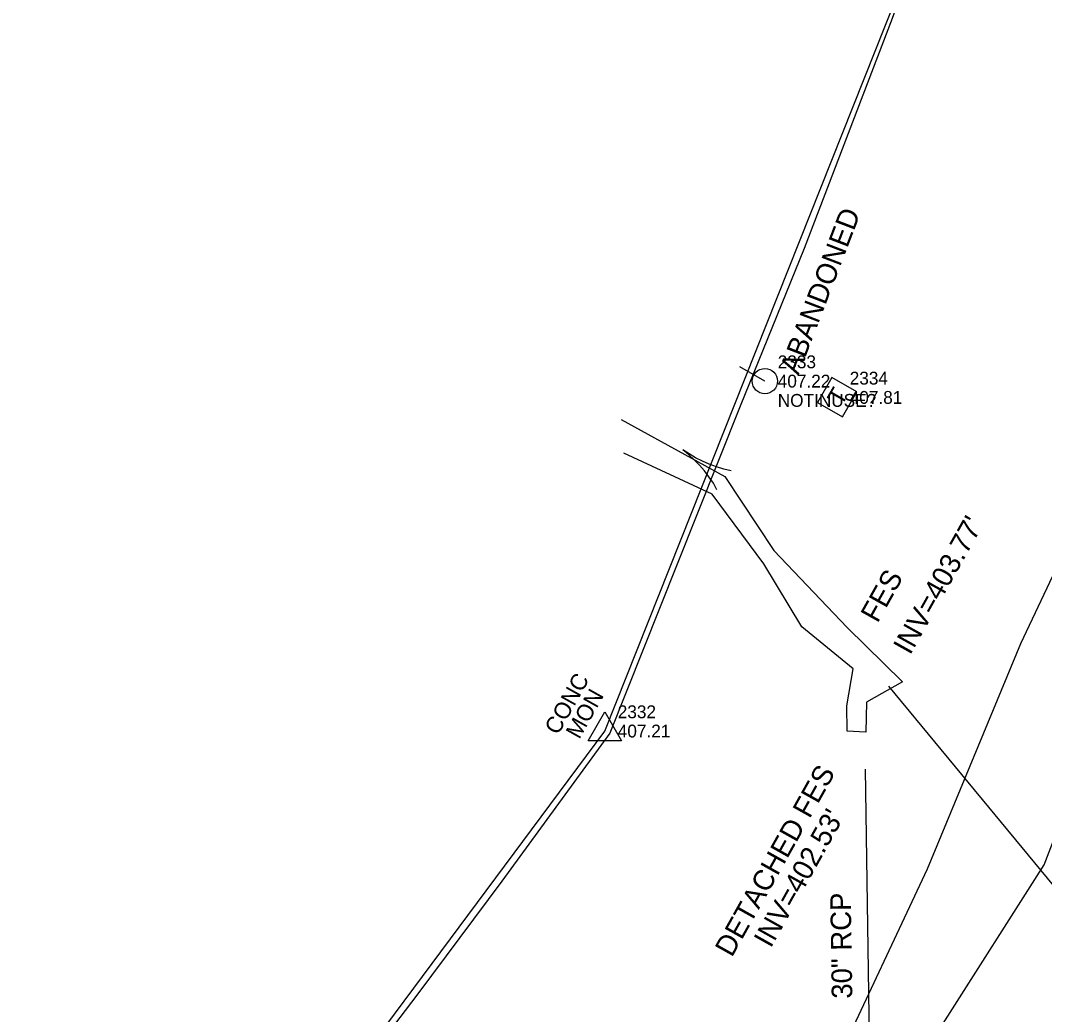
# Model space of a CAD drawing. Extents: x 2074109 to 2077820, y 741079 to 746031.
# Drawn here: x 2075888.4 to 2076087.4, y 744709.8 to 744903 of the extents above; entities that cross this region are included whole.
import ezdxf

# ---------------------------------------------------------------- set-up
doc = ezdxf.new("R2010")
doc.units = 0
for name, color, linetype in [('Exist Horizontal Alignment', 7, 'Continuous'), ('Exist Hydro Stream Flow Arrow CELL', 7, 'Continuous'), ('Exist Hydro Stream or Body of Water', 7, 'Continuous'), ('Exist Other Culture Fence Line', 7, 'Continuous'), ('Exist Right of Way Line', 7, 'Continuous'), ('Exist Right of Way Monument CELL', 7, 'Continuous'), ('Exist Right of Way Monument Cogo Elevation', 7, 'Continuous'), ('Exist Right of Way Monument Cogo Number', 7, 'Continuous'), ('Exist Right of Way Monument Text', 7, 'Continuous'), ('Exist Structure Minor Pipes RCP 30 Inch', 7, 'Continuous'), ('Exist Structure Minor Pipes RCP 30 Inch Invert', 7, 'Continuous'), ('Exist Structure Minor Pipes RCP 30 Inch Text', 7, 'Continuous'), ('Exist Structure Minor Pipes RCP 48 Inch', 7, 'Continuous'), ('Exist Structure Minor Pipes RCP 48 Inch Invert', 7, 'Continuous'), ('Exist Utilities Power Pole CELL', 7, 'Continuous'), ('Exist Utilities Power Pole Cogo Comment', 7, 'Continuous'), ('Exist Utilities Power Pole Cogo Elevation', 7, 'Continuous'), ('Exist Utilities Power Pole Cogo Number', 7, 'Continuous'), ('Exist Utilities Power Pole Text', 7, 'Continuous'), ('Exist Utilities Telephone Pedestal CELL', 7, 'Continuous'), ('Exist Utilities Telephone Pedestal Cogo Elevation', 7, 'Continuous'), ('Exist Utilities Telephone Pedestal Cogo Number', 7, 'Continuous'), ('Exist Utilities Telephone UG FO SUE LOS B', 7, 'Continuous'), ('Exist Vegetation Woods Line', 7, 'Continuous')]:
    doc.layers.add(name, color=color, linetype=linetype)

msp = doc.modelspace()

# ---------------------------------------------------------------- linework, layer by layer
at = {"layer": 'Exist Horizontal Alignment'}
for centre, radius, start, end in [((2065746.77, 748969.72), 11283.45, 330.581241, 339.398504), ((2074798.58, 745361.18), 1469.76, 306.18995, 339.08912)]:
    msp.add_arc(centre, radius, start, end, dxfattribs=at)
at = {"layer": 'Exist Hydro Stream Flow Arrow CELL'}
msp.add_line((2076021.1, 744816.63), (2076021.1, 744816.63), dxfattribs=at)
for points in [[(2076026.48, 744815.48), (2076025.05, 744815.8), (2076023.63, 744816.28), (2076022.24, 744816.77), (2076020.92, 744817.36), (2076019.6, 744818.04), (2076018.31, 744818.8), (2076017.09, 744819.61)], [(2076023.75, 744811.81), (2076023.04, 744813.09), (2076022.17, 744814.31), (2076021.3, 744815.5), (2076020.35, 744816.6), (2076019.32, 744817.66), (2076018.22, 744818.68), (2076017.09, 744819.61)]]:
    msp.add_lwpolyline(points, dxfattribs=at)
at = {"layer": 'Exist Hydro Stream or Body of Water'}
msp.add_lwpolyline([(2076005.14, 744825.46), (2076025.25, 744814.37), (2076034.83, 744800), (2076049.07, 744785.06), (2076059.84, 744774.47), (2076052.8, 744770.53), (2076052.7, 744764.69), (2076049.04, 744764.89), (2076049, 744769.8), (2076050.21, 744776.99), (2076040.24, 744785.17), (2076032.88, 744797.42), (2076022.8, 744810.99), (2076005.61, 744818.96)], dxfattribs=at)
at = {"layer": 'Exist Other Culture Fence Line'}
msp.add_lwpolyline([(2076162.42, 745176.79), (2076145.19, 745130.51), (2076128.17, 745085.01), (2076111.58, 745041.43), (2076096.68, 745003.97), (2076079.15, 744957.46), (2076063.26, 744918.47), (2076057.81, 744903.45), (2076040.7, 744858.73), (2076028.24, 744828.04), (2076015.85, 744797.06), (2076002.89, 744764.52), (2075981.92, 744735.72), (2075965.57, 744713.81), (2075953.66, 744698.14), (2075926.24, 744660.83), (2075903.14, 744629.48), (2075873.54, 744589.85)], dxfattribs=at)
at = {"layer": 'Exist Right of Way Line'}
for p, q in [((2076001.96, 744764.91), (2076072.08, 744941.45)), ((2075770.83, 744453.88), (2076001.96, 744764.91)), ((2076001.96, 744764.91), (2076001.96, 744764.91))]:
    msp.add_line(p, q, dxfattribs=at)
at = {"layer": 'Exist Right of Way Monument CELL'}
msp.add_line((2076001.96, 744764.91), (2076001.96, 744764.91), dxfattribs=at)
msp.add_lwpolyline([(2075998.71, 744763.02), (2076001.96, 744768.66), (2076005.2, 744763.02)], close=True, dxfattribs=at)
at = {"layer": 'Exist Structure Minor Pipes RCP 30 Inch'}
msp.add_line((2076053.85, 744676.49), (2076052.65, 744757.49), dxfattribs=at)
at = {"layer": 'Exist Structure Minor Pipes RCP 48 Inch'}
msp.add_line((2076057.12, 744773.62), (2076166.6, 744640.93), dxfattribs=at)
at = {"layer": 'Exist Utilities Power Pole CELL'}
for q in [(2076028.17, 744835.73), (2076033.06, 744832.94)]:
    msp.add_line((2076033.06, 744832.94), q, dxfattribs=at)
msp.add_circle((2076033.06, 744832.94), 2.45, dxfattribs=at)
at = {"layer": 'Exist Utilities Telephone Pedestal CELL'}
msp.add_line((2076047.05, 744829.77), (2076047.05, 744829.77), dxfattribs=at)
msp.add_lwpolyline([(2076048.15, 744826), (2076050.92, 744830.86), (2076046.06, 744833.63), (2076043.29, 744828.77), (2076048.15, 744826)], dxfattribs=at)
at = {"layer": 'Exist Utilities Telephone UG FO SUE LOS B'}
msp.add_lwpolyline([(2075937.23, 744341.86), (2075954.9, 744371.47), (2075967.47, 744402.74), (2075973.95, 744427.85), (2075977.39, 744451.86), (2075976.07, 744468.29), (2075977.43, 744509.14), (2075977.11, 744533.46), (2075991.55, 744563.05), (2076030.62, 744642.2), (2076067.73, 744708.03), (2076087.38, 744738.93), (2076104.62, 744783.9), (2076126.25, 744837.76), (2076148.02, 744890.9), (2076167.98, 744943.19), (2076197.47, 745025.67)], dxfattribs=at)
at = {"layer": 'Exist Vegetation Woods Line'}
msp.add_lwpolyline([(2076198.02, 745068.71), (2076197.63, 745067.83), (2076187.37, 745031.7), (2076171.82, 744988.45), (2076156.95, 744953.13), (2076140.48, 744910.01), (2076121.87, 744862.5), (2076100.31, 744819.01), (2076082.73, 744781.89), (2076064.59, 744738.03), (2076046.8, 744700.12), (2076035.25, 744661.7)], dxfattribs=at)

# ---------------------------------------------------------------- texts
at = {"layer": 'Exist Right of Way Monument Cogo Elevation'}
msp.add_text('407.21', height=2.5, dxfattribs=at).set_placement((2076004.46, 744763.66))
at = {"layer": 'Exist Right of Way Monument Cogo Number'}
msp.add_text('2332', height=2.5, dxfattribs=at).set_placement((2076004.46, 744767.41))
at = {"layer": 'Exist Right of Way Monument Text'}
for s, p in [('CONC', (2075992.85, 744763.99)), ('MON', (2075996.98, 744763.18))]:
    msp.add_text(s, height=3.2, rotation=60.742, dxfattribs=at).set_placement(p)
at = {"layer": 'Exist Structure Minor Pipes RCP 30 Inch Invert'}
msp.add_text("INV=402.53'", height=4, rotation=60.7411, dxfattribs=at).set_placement((2076034.19, 744722.57))
at = {"layer": 'Exist Structure Minor Pipes RCP 30 Inch Text'}
msp.add_text('30" RCP', height=4, rotation=90.8452, dxfattribs=at).set_placement((2076050.06, 744712.91))
at = {"layer": 'Exist Structure Minor Pipes RCP 48 Inch Invert'}
for s, p in [("INV=403.77'", (2076061.29, 744779.54)), ('FES', (2076054.96, 744785.75)), ('DETACHED FES', (2076026.64, 744720.78))]:
    msp.add_text(s, height=4, rotation=60.7411, dxfattribs=at).set_placement(p)
at = {"layer": 'Exist Utilities Power Pole Cogo Comment'}
msp.add_text('NOTINUSE?', height=2.5, dxfattribs=at).set_placement((2076035.56, 744827.94))
at = {"layer": 'Exist Utilities Power Pole Cogo Elevation'}
msp.add_text('407.22', height=2.5, dxfattribs=at).set_placement((2076035.56, 744831.69))
at = {"layer": 'Exist Utilities Power Pole Cogo Number'}
msp.add_text('2333', height=2.5, dxfattribs=at).set_placement((2076035.56, 744835.44))
at = {"layer": 'Exist Utilities Power Pole Text'}
msp.add_text('ABANDONED', height=4, rotation=68.9996, dxfattribs=at).set_placement((2076039.58, 744833.98))
at = {"layer": 'Exist Utilities Telephone Pedestal CELL'}
msp.add_text('T', height=3.42, rotation=60.3375, dxfattribs=at).set_placement((2076047.98, 744827.94))
at = {"layer": 'Exist Utilities Telephone Pedestal Cogo Elevation'}
msp.add_text('407.81', height=2.5, dxfattribs=at).set_placement((2076049.55, 744828.52))
at = {"layer": 'Exist Utilities Telephone Pedestal Cogo Number'}
msp.add_text('2334', height=2.5, dxfattribs=at).set_placement((2076049.55, 744832.27))

doc.saveas('drawing.dxf')
